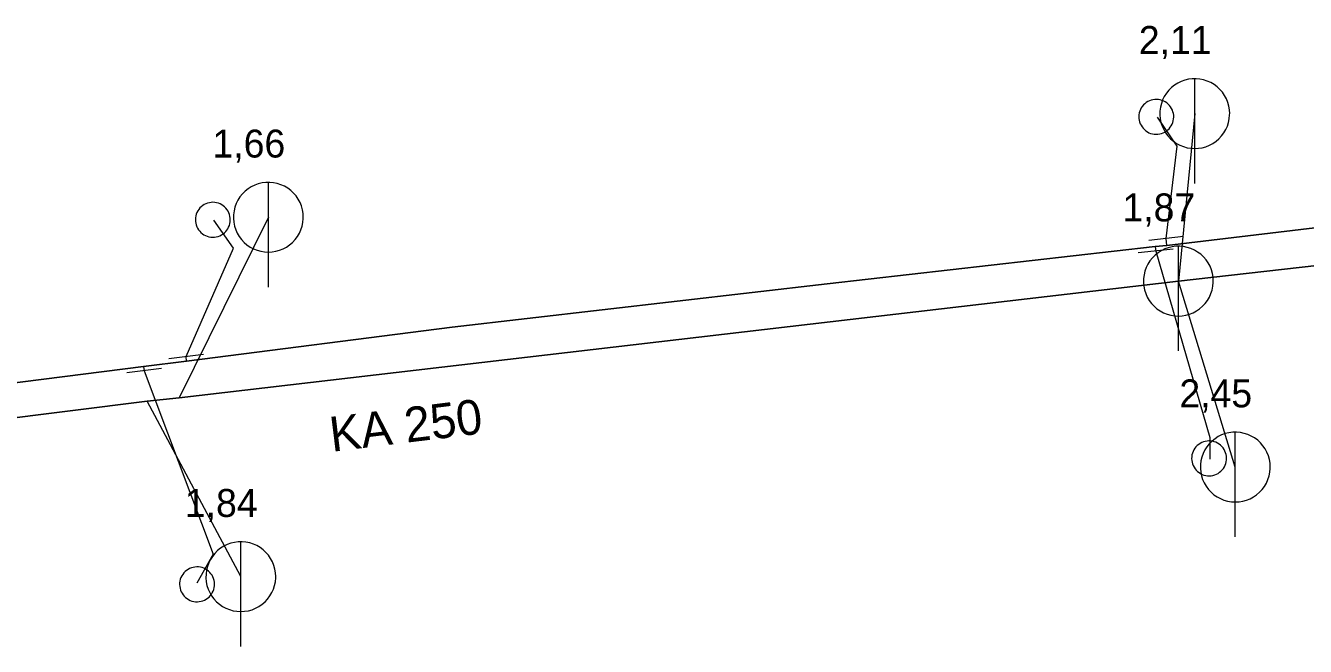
# Model space of a CAD drawing. Extents: x -682839 to -682312, y -994645 to -993949.
# Drawn here: x -682654.47 to -682617.83, y -994270.55 to -994252.76 of the extents above; entities that cross this region are included whole.
import ezdxf

# ---------------------------------------------------------------- set-up
doc = ezdxf.new("R2010")
doc.units = 0
doc.header["$LTSCALE"] = 0.4
doc.layers.add('1', color=7, linetype='Continuous')
for name, color, linetype, lineweight in [('11', 7, 'Continuous', 13), ('13', 7, 'Continuous', 13), ('14', 7, 'Continuous', 25), ('17', 7, 'Continuous', 25), ('22', 7, 'Continuous', 13), ('23', 7, 'Continuous', 13), ('34', 7, 'Continuous', 13)]:
    doc.layers.add(name, color=color, linetype=linetype, lineweight=lineweight)

msp = doc.modelspace()

# ---------------------------------------------------------------- linework, layer by layer
at = {"layer": '11'}
for p, q in [((-682621, -994255.28), (-682621.469, -994260.079)), ((-682647.52, -994258.25), (-682650.07, -994263.421)), ((-682619.84, -994265.41), (-682621.469, -994260.079)), ((-682648.309, -994268.55), (-682650.991, -994263.524))]:
    msp.add_line(p, q, dxfattribs=at)
at = {"layer": '13'}
for points in [[(-682621.819, -994258.859), (-682621.5, -994256.21), (-682622.069, -994255.379)], [(-682649.876, -994262.245), (-682648.52, -994259.14), (-682649.079, -994258.329)], [(-682622.119, -994259.219), (-682620.57, -994264.559), (-682620.567, -994265.183)], [(-682651.079, -994262.649), (-682649.1, -994267.91), (-682649.57, -994268.739)]]:
    msp.add_lwpolyline(points, dxfattribs=at)
at = {"layer": '14'}
msp.add_line((-682595.359, -994257.109), (-682621.469, -994260.079), dxfattribs=at)
at = {"layer": '14', "lineweight": 13}
for p, q in [((-682622.134, -994259.092), (-682622.119, -994259.219)), ((-682621.798, -994259.055), (-682621.819, -994258.859)), ((-682649.861, -994262.37), (-682649.876, -994262.245)), ((-682651.096, -994262.526), (-682651.079, -994262.649))]:
    msp.add_line(p, q, dxfattribs=at)
at = {"layer": '14'}
msp.add_lwpolyline([(-682621.469, -994260.079), (-682650.07, -994263.421), (-682650.991, -994263.524), (-682664.452, -994265.215)], dxfattribs=at)
at = {"layer": '17'}
msp.add_lwpolyline([(-682575, -994253.756), (-682585.09, -994254.838), (-682594.877, -994255.783), (-682595.977, -994255.888), (-682601.16, -994256.39), (-682606.69, -994257.25), (-682621.798, -994259.055), (-682622.134, -994259.092), (-682631.52, -994260.16), (-682642.26, -994261.399), (-682649.861, -994262.37), (-682651.096, -994262.526), (-682656.289, -994263.19), (-682658.389, -994263.379)], dxfattribs=at)
at = {"layer": '22'}
for p, q in [((-682621, -994257.28), (-682620.999, -994254.28)), ((-682647.52, -994260.25), (-682647.519, -994257.25)), ((-682621.47, -994262.08), (-682621.469, -994259.08)), ((-682619.84, -994267.41), (-682619.839, -994264.41)), ((-682648.309, -994270.55), (-682648.308, -994267.55))]:
    msp.add_line(p, q, dxfattribs=at)
for points in [[(-682620, -994255.28), (-682620.005, -994255.171), (-682620.023, -994255.063), (-682620.053, -994254.957), (-682620.093, -994254.856), (-682620.145, -994254.759), (-682620.207, -994254.669), (-682620.279, -994254.586), (-682620.359, -994254.512), (-682620.447, -994254.446), (-682620.541, -994254.391), (-682620.641, -994254.346), (-682620.746, -994254.313), (-682620.853, -994254.291), (-682620.962, -994254.281), (-682621.072, -994254.283), (-682621.18, -994254.297), (-682621.287, -994254.322), (-682621.39, -994254.359), (-682621.488, -994254.408), (-682621.58, -994254.466), (-682621.666, -994254.535), (-682621.743, -994254.612), (-682621.812, -994254.698), (-682621.871, -994254.79), (-682621.919, -994254.888), (-682621.956, -994254.991), (-682621.982, -994255.098), (-682621.996, -994255.206), (-682621.999, -994255.316), (-682621.989, -994255.425), (-682621.968, -994255.532), (-682621.934, -994255.636), (-682621.89, -994255.736), (-682621.835, -994255.831), (-682621.769, -994255.919), (-682621.695, -994255.999), (-682621.612, -994256.071), (-682621.522, -994256.133), (-682621.426, -994256.185), (-682621.324, -994256.226), (-682621.219, -994256.256), (-682621.111, -994256.274), (-682621.001, -994256.28), (-682620.892, -994256.274), (-682620.784, -994256.256), (-682620.679, -994256.227), (-682620.577, -994256.186), (-682620.48, -994256.134), (-682620.39, -994256.072), (-682620.307, -994256.001), (-682620.232, -994255.921), (-682620.167, -994255.833), (-682620.111, -994255.739), (-682620.067, -994255.639), (-682620.033, -994255.535), (-682620.011, -994255.427), (-682620.001, -994255.318)], [(-682646.52, -994258.25), (-682646.525, -994258.141), (-682646.543, -994258.033), (-682646.573, -994257.927), (-682646.613, -994257.826), (-682646.665, -994257.729), (-682646.727, -994257.639), (-682646.799, -994257.556), (-682646.879, -994257.482), (-682646.967, -994257.416), (-682647.061, -994257.361), (-682647.161, -994257.316), (-682647.266, -994257.283), (-682647.373, -994257.261), (-682647.482, -994257.251), (-682647.592, -994257.253), (-682647.7, -994257.267), (-682647.807, -994257.292), (-682647.91, -994257.329), (-682648.008, -994257.378), (-682648.1, -994257.436), (-682648.186, -994257.505), (-682648.263, -994257.582), (-682648.332, -994257.668), (-682648.391, -994257.76), (-682648.439, -994257.858), (-682648.476, -994257.961), (-682648.502, -994258.068), (-682648.516, -994258.176), (-682648.519, -994258.286), (-682648.509, -994258.395), (-682648.488, -994258.502), (-682648.454, -994258.606), (-682648.41, -994258.706), (-682648.355, -994258.801), (-682648.289, -994258.889), (-682648.215, -994258.969), (-682648.132, -994259.041), (-682648.042, -994259.103), (-682647.946, -994259.155), (-682647.844, -994259.196), (-682647.739, -994259.226), (-682647.631, -994259.244), (-682647.521, -994259.25), (-682647.412, -994259.244), (-682647.304, -994259.226), (-682647.199, -994259.197), (-682647.097, -994259.156), (-682647, -994259.104), (-682646.91, -994259.042), (-682646.827, -994258.971), (-682646.752, -994258.891), (-682646.687, -994258.803), (-682646.631, -994258.709), (-682646.587, -994258.609), (-682646.553, -994258.505), (-682646.531, -994258.397), (-682646.521, -994258.288)], [(-682620.47, -994260.08), (-682620.475, -994259.971), (-682620.493, -994259.863), (-682620.523, -994259.757), (-682620.563, -994259.656), (-682620.615, -994259.559), (-682620.677, -994259.469), (-682620.749, -994259.386), (-682620.829, -994259.312), (-682620.917, -994259.246), (-682621.011, -994259.191), (-682621.111, -994259.146), (-682621.216, -994259.113), (-682621.323, -994259.091), (-682621.432, -994259.081), (-682621.542, -994259.083), (-682621.65, -994259.097), (-682621.757, -994259.122), (-682621.86, -994259.159), (-682621.958, -994259.208), (-682622.05, -994259.266), (-682622.136, -994259.335), (-682622.213, -994259.412), (-682622.282, -994259.498), (-682622.341, -994259.59), (-682622.389, -994259.688), (-682622.426, -994259.791), (-682622.452, -994259.898), (-682622.466, -994260.006), (-682622.469, -994260.116), (-682622.459, -994260.225), (-682622.438, -994260.332), (-682622.404, -994260.436), (-682622.36, -994260.536), (-682622.305, -994260.631), (-682622.239, -994260.719), (-682622.165, -994260.799), (-682622.082, -994260.871), (-682621.992, -994260.933), (-682621.896, -994260.985), (-682621.794, -994261.026), (-682621.689, -994261.056), (-682621.581, -994261.074), (-682621.471, -994261.08), (-682621.362, -994261.074), (-682621.254, -994261.056), (-682621.149, -994261.027), (-682621.047, -994260.986), (-682620.95, -994260.934), (-682620.86, -994260.872), (-682620.777, -994260.801), (-682620.702, -994260.721), (-682620.637, -994260.633), (-682620.581, -994260.539), (-682620.537, -994260.439), (-682620.503, -994260.335), (-682620.481, -994260.227), (-682620.471, -994260.118)], [(-682618.84, -994265.41), (-682618.845, -994265.301), (-682618.863, -994265.193), (-682618.893, -994265.087), (-682618.933, -994264.986), (-682618.985, -994264.889), (-682619.047, -994264.799), (-682619.119, -994264.716), (-682619.199, -994264.642), (-682619.287, -994264.576), (-682619.381, -994264.521), (-682619.481, -994264.476), (-682619.586, -994264.443), (-682619.693, -994264.421), (-682619.802, -994264.411), (-682619.912, -994264.413), (-682620.02, -994264.427), (-682620.127, -994264.452), (-682620.23, -994264.489), (-682620.328, -994264.538), (-682620.42, -994264.596), (-682620.506, -994264.665), (-682620.583, -994264.742), (-682620.652, -994264.828), (-682620.711, -994264.92), (-682620.759, -994265.018), (-682620.796, -994265.121), (-682620.822, -994265.228), (-682620.836, -994265.336), (-682620.839, -994265.446), (-682620.829, -994265.555), (-682620.808, -994265.662), (-682620.774, -994265.766), (-682620.73, -994265.866), (-682620.675, -994265.961), (-682620.609, -994266.049), (-682620.535, -994266.129), (-682620.452, -994266.201), (-682620.362, -994266.263), (-682620.266, -994266.315), (-682620.164, -994266.356), (-682620.059, -994266.386), (-682619.951, -994266.404), (-682619.841, -994266.41), (-682619.732, -994266.404), (-682619.624, -994266.386), (-682619.519, -994266.357), (-682619.417, -994266.316), (-682619.32, -994266.264), (-682619.23, -994266.202), (-682619.147, -994266.131), (-682619.072, -994266.051), (-682619.007, -994265.963), (-682618.951, -994265.869), (-682618.907, -994265.769), (-682618.873, -994265.665), (-682618.851, -994265.557), (-682618.841, -994265.448)], [(-682647.309, -994268.55), (-682647.314, -994268.441), (-682647.332, -994268.333), (-682647.362, -994268.227), (-682647.402, -994268.126), (-682647.454, -994268.029), (-682647.516, -994267.939), (-682647.588, -994267.856), (-682647.668, -994267.782), (-682647.756, -994267.716), (-682647.85, -994267.661), (-682647.95, -994267.616), (-682648.055, -994267.583), (-682648.162, -994267.561), (-682648.271, -994267.551), (-682648.381, -994267.553), (-682648.489, -994267.567), (-682648.596, -994267.592), (-682648.699, -994267.629), (-682648.797, -994267.678), (-682648.889, -994267.736), (-682648.975, -994267.805), (-682649.052, -994267.882), (-682649.121, -994267.968), (-682649.18, -994268.06), (-682649.228, -994268.158), (-682649.265, -994268.261), (-682649.291, -994268.368), (-682649.305, -994268.476), (-682649.308, -994268.586), (-682649.298, -994268.695), (-682649.277, -994268.802), (-682649.243, -994268.906), (-682649.199, -994269.006), (-682649.144, -994269.101), (-682649.078, -994269.189), (-682649.004, -994269.269), (-682648.921, -994269.341), (-682648.831, -994269.403), (-682648.735, -994269.455), (-682648.633, -994269.496), (-682648.528, -994269.526), (-682648.42, -994269.544), (-682648.31, -994269.55), (-682648.201, -994269.544), (-682648.093, -994269.526), (-682647.988, -994269.497), (-682647.886, -994269.456), (-682647.789, -994269.404), (-682647.699, -994269.342), (-682647.616, -994269.271), (-682647.541, -994269.191), (-682647.476, -994269.103), (-682647.42, -994269.009), (-682647.376, -994268.909), (-682647.342, -994268.805), (-682647.32, -994268.697), (-682647.31, -994268.588)]]:
    msp.add_lwpolyline(points, close=True, dxfattribs=at)
at = {"layer": '23'}
for points in [[(-682621.813, -994255.782), (-682621.771, -994255.749), (-682621.733, -994255.712), (-682621.701, -994255.672), (-682621.672, -994255.629), (-682621.647, -994255.583), (-682621.628, -994255.533), (-682621.614, -994255.483), (-682621.605, -994255.433), (-682621.601, -994255.38), (-682621.603, -994255.328), (-682621.61, -994255.276), (-682621.623, -994255.224), (-682621.641, -994255.176), (-682621.664, -994255.13), (-682621.691, -994255.085), (-682621.725, -994255.043), (-682621.759, -994255.006), (-682621.801, -994254.972), (-682621.843, -994254.943), (-682621.889, -994254.918), (-682621.94, -994254.899), (-682621.989, -994254.885), (-682622.042, -994254.876), (-682622.093, -994254.872), (-682622.145, -994254.874), (-682622.198, -994254.882), (-682622.247, -994254.895), (-682622.297, -994254.913), (-682622.344, -994254.937), (-682622.388, -994254.964), (-682622.429, -994254.995), (-682622.467, -994255.032), (-682622.501, -994255.073), (-682622.53, -994255.116), (-682622.553, -994255.162), (-682622.573, -994255.21), (-682622.588, -994255.261), (-682622.597, -994255.313), (-682622.6, -994255.365)], [(-682621.801, -994254.972), (-682621.843, -994254.943), (-682621.889, -994254.918), (-682621.94, -994254.899), (-682621.989, -994254.885), (-682622.042, -994254.876), (-682622.093, -994254.872), (-682622.145, -994254.874), (-682622.198, -994254.882), (-682622.247, -994254.895), (-682622.297, -994254.913), (-682622.344, -994254.937), (-682622.388, -994254.964), (-682622.429, -994254.995), (-682622.467, -994255.032), (-682622.501, -994255.073), (-682622.53, -994255.116), (-682622.553, -994255.162), (-682622.573, -994255.21), (-682622.588, -994255.261), (-682622.597, -994255.313), (-682622.6, -994255.365), (-682622.599, -994255.416), (-682622.591, -994255.469), (-682622.579, -994255.519), (-682622.559, -994255.569), (-682622.536, -994255.615), (-682622.509, -994255.659), (-682622.477, -994255.7), (-682622.441, -994255.738), (-682622.4, -994255.773), (-682622.357, -994255.801), (-682622.31, -994255.826), (-682622.263, -994255.846), (-682622.211, -994255.859), (-682622.161, -994255.869), (-682622.109, -994255.872), (-682622.055, -994255.87), (-682622.003, -994255.863), (-682621.953, -994255.85)], [(-682622.6, -994255.365), (-682622.599, -994255.416), (-682622.591, -994255.469), (-682622.579, -994255.519), (-682622.559, -994255.569), (-682622.536, -994255.615), (-682622.509, -994255.659), (-682622.477, -994255.7), (-682622.441, -994255.738), (-682622.4, -994255.773), (-682622.357, -994255.801), (-682622.31, -994255.826), (-682622.263, -994255.846), (-682622.211, -994255.859), (-682622.161, -994255.869), (-682622.109, -994255.872), (-682622.055, -994255.87), (-682622.003, -994255.863), (-682621.953, -994255.85), (-682621.904, -994255.831), (-682621.857, -994255.809), (-682621.813, -994255.782), (-682621.771, -994255.749), (-682621.733, -994255.712), (-682621.701, -994255.672), (-682621.672, -994255.629), (-682621.647, -994255.583), (-682621.628, -994255.533), (-682621.614, -994255.483), (-682621.605, -994255.433), (-682621.601, -994255.38), (-682621.603, -994255.328), (-682621.61, -994255.276), (-682621.623, -994255.224), (-682621.641, -994255.176), (-682621.664, -994255.13), (-682621.691, -994255.085), (-682621.725, -994255.043), (-682621.759, -994255.006), (-682621.801, -994254.972)], [(-682621.953, -994255.85), (-682621.904, -994255.831), (-682621.857, -994255.809), (-682621.813, -994255.782)], [(-682648.822, -994258.731), (-682648.78, -994258.698), (-682648.742, -994258.661), (-682648.71, -994258.621), (-682648.681, -994258.578), (-682648.657, -994258.532), (-682648.637, -994258.482), (-682648.623, -994258.432), (-682648.615, -994258.381), (-682648.611, -994258.329), (-682648.613, -994258.277), (-682648.62, -994258.224), (-682648.634, -994258.173), (-682648.651, -994258.124), (-682648.675, -994258.078), (-682648.702, -994258.034), (-682648.736, -994257.992), (-682648.771, -994257.955), (-682648.813, -994257.921), (-682648.854, -994257.893), (-682648.901, -994257.868), (-682648.951, -994257.849), (-682649.001, -994257.835), (-682649.053, -994257.826), (-682649.105, -994257.822), (-682649.157, -994257.824), (-682649.209, -994257.833), (-682649.259, -994257.845), (-682649.308, -994257.864), (-682649.355, -994257.887), (-682649.399, -994257.915), (-682649.44, -994257.947), (-682649.478, -994257.984), (-682649.512, -994258.024), (-682649.541, -994258.067), (-682649.564, -994258.113), (-682649.583, -994258.162), (-682649.598, -994258.212), (-682649.607, -994258.265), (-682649.61, -994258.317)], [(-682648.813, -994257.921), (-682648.854, -994257.893), (-682648.901, -994257.868), (-682648.951, -994257.849), (-682649.001, -994257.835), (-682649.053, -994257.826), (-682649.105, -994257.822), (-682649.157, -994257.824), (-682649.209, -994257.833), (-682649.259, -994257.845), (-682649.308, -994257.864), (-682649.355, -994257.887), (-682649.399, -994257.915), (-682649.44, -994257.947), (-682649.478, -994257.984), (-682649.512, -994258.024), (-682649.541, -994258.067), (-682649.564, -994258.113), (-682649.583, -994258.162), (-682649.598, -994258.212), (-682649.607, -994258.265), (-682649.61, -994258.317), (-682649.609, -994258.368), (-682649.6, -994258.421), (-682649.589, -994258.471), (-682649.569, -994258.52), (-682649.546, -994258.566), (-682649.519, -994258.611), (-682649.486, -994258.651), (-682649.45, -994258.69), (-682649.409, -994258.724), (-682649.365, -994258.752), (-682649.319, -994258.777), (-682649.271, -994258.796), (-682649.22, -994258.809), (-682649.169, -994258.819), (-682649.117, -994258.822), (-682649.064, -994258.82), (-682649.012, -994258.813), (-682648.961, -994258.799)], [(-682649.61, -994258.317), (-682649.609, -994258.368), (-682649.6, -994258.421), (-682649.589, -994258.471), (-682649.569, -994258.52), (-682649.546, -994258.566), (-682649.519, -994258.611), (-682649.486, -994258.651), (-682649.45, -994258.69), (-682649.409, -994258.724), (-682649.365, -994258.752), (-682649.319, -994258.777), (-682649.271, -994258.796), (-682649.22, -994258.809), (-682649.169, -994258.819), (-682649.117, -994258.822), (-682649.064, -994258.82), (-682649.012, -994258.813), (-682648.961, -994258.799), (-682648.913, -994258.78), (-682648.866, -994258.758), (-682648.822, -994258.731), (-682648.78, -994258.698), (-682648.742, -994258.661), (-682648.71, -994258.621), (-682648.681, -994258.578), (-682648.657, -994258.532), (-682648.637, -994258.482), (-682648.623, -994258.432), (-682648.615, -994258.381), (-682648.611, -994258.329), (-682648.613, -994258.277), (-682648.62, -994258.224), (-682648.634, -994258.173), (-682648.651, -994258.124), (-682648.675, -994258.078), (-682648.702, -994258.034), (-682648.736, -994257.992), (-682648.771, -994257.955), (-682648.813, -994257.921)], [(-682648.961, -994258.799), (-682648.913, -994258.78), (-682648.866, -994258.758), (-682648.822, -994258.731)], [(-682620.117, -994264.997), (-682620.135, -994264.95), (-682620.159, -994264.903), (-682620.19, -994264.859), (-682620.223, -994264.819), (-682620.261, -994264.783), (-682620.301, -994264.75), (-682620.345, -994264.723), (-682620.394, -994264.7), (-682620.442, -994264.682), (-682620.493, -994264.669), (-682620.545, -994264.662), (-682620.597, -994264.66), (-682620.649, -994264.663), (-682620.701, -994264.672), (-682620.752, -994264.686), (-682620.8, -994264.705), (-682620.844, -994264.73), (-682620.888, -994264.76), (-682620.929, -994264.793), (-682620.966, -994264.831), (-682620.998, -994264.872), (-682621.026, -994264.915), (-682621.049, -994264.963), (-682621.068, -994265.011), (-682621.079, -994265.063), (-682621.086, -994265.114), (-682621.089, -994265.166), (-682621.085, -994265.218), (-682621.077, -994265.27), (-682621.063, -994265.321), (-682621.042, -994265.369), (-682621.018, -994265.416), (-682620.99, -994265.459), (-682620.955, -994265.499), (-682620.919, -994265.536), (-682620.878, -994265.568), (-682620.833, -994265.596), (-682620.786, -994265.619), (-682620.737, -994265.637)], [(-682620.998, -994264.872), (-682621.026, -994264.915), (-682621.049, -994264.963), (-682621.068, -994265.011), (-682621.079, -994265.063), (-682621.086, -994265.114), (-682621.089, -994265.166), (-682621.085, -994265.218), (-682621.077, -994265.27), (-682621.063, -994265.321), (-682621.042, -994265.369), (-682621.018, -994265.416), (-682620.99, -994265.459), (-682620.955, -994265.499), (-682620.919, -994265.536), (-682620.878, -994265.568), (-682620.833, -994265.596), (-682620.786, -994265.619), (-682620.737, -994265.637), (-682620.686, -994265.649), (-682620.634, -994265.657), (-682620.582, -994265.66), (-682620.529, -994265.656), (-682620.478, -994265.647), (-682620.429, -994265.632), (-682620.38, -994265.613), (-682620.334, -994265.589), (-682620.29, -994265.559), (-682620.25, -994265.525), (-682620.214, -994265.488), (-682620.181, -994265.447), (-682620.153, -994265.403), (-682620.129, -994265.356), (-682620.112, -994265.306), (-682620.099, -994265.256), (-682620.092, -994265.205), (-682620.089, -994265.153), (-682620.093, -994265.099), (-682620.101, -994265.049), (-682620.117, -994264.997)], [(-682620.582, -994265.66), (-682620.529, -994265.656), (-682620.478, -994265.647), (-682620.429, -994265.632), (-682620.38, -994265.613), (-682620.334, -994265.589), (-682620.29, -994265.559), (-682620.25, -994265.525), (-682620.214, -994265.488), (-682620.181, -994265.447), (-682620.153, -994265.403), (-682620.129, -994265.356), (-682620.112, -994265.306), (-682620.099, -994265.256), (-682620.092, -994265.205), (-682620.089, -994265.153), (-682620.093, -994265.099), (-682620.101, -994265.049), (-682620.117, -994264.997), (-682620.135, -994264.95), (-682620.159, -994264.903), (-682620.19, -994264.859), (-682620.223, -994264.819), (-682620.261, -994264.783), (-682620.301, -994264.75), (-682620.345, -994264.723), (-682620.394, -994264.7), (-682620.442, -994264.682), (-682620.493, -994264.669), (-682620.545, -994264.662), (-682620.597, -994264.66), (-682620.649, -994264.663), (-682620.701, -994264.672), (-682620.752, -994264.686), (-682620.8, -994264.705), (-682620.844, -994264.73), (-682620.888, -994264.76), (-682620.929, -994264.793), (-682620.966, -994264.831), (-682620.998, -994264.872)], [(-682620.737, -994265.637), (-682620.686, -994265.649), (-682620.634, -994265.657), (-682620.582, -994265.66)], [(-682649.319, -994268.332), (-682649.367, -994268.309), (-682649.417, -994268.291), (-682649.467, -994268.28), (-682649.519, -994268.272), (-682649.57, -994268.27), (-682649.623, -994268.275), (-682649.675, -994268.284), (-682649.724, -994268.298), (-682649.773, -994268.318), (-682649.819, -994268.342), (-682649.863, -994268.371), (-682649.903, -994268.406), (-682649.939, -994268.443), (-682649.971, -994268.484), (-682649.999, -994268.528), (-682650.022, -994268.577), (-682650.04, -994268.624), (-682650.052, -994268.677), (-682650.06, -994268.726), (-682650.062, -994268.779), (-682650.057, -994268.833), (-682650.048, -994268.884), (-682650.033, -994268.935), (-682650.014, -994268.983), (-682649.989, -994269.028), (-682649.959, -994269.072), (-682649.926, -994269.111), (-682649.888, -994269.148), (-682649.846, -994269.179), (-682649.802, -994269.208), (-682649.756, -994269.231), (-682649.706, -994269.248), (-682649.655, -994269.261), (-682649.604, -994269.269), (-682649.552, -994269.269), (-682649.5, -994269.265), (-682649.448, -994269.257), (-682649.397, -994269.242), (-682649.349, -994269.222)], [(-682649.349, -994269.222), (-682649.303, -994269.198), (-682649.259, -994269.168), (-682649.219, -994269.136), (-682649.183, -994269.096), (-682649.152, -994269.055), (-682649.124, -994269.012), (-682649.102, -994268.964), (-682649.083, -994268.915), (-682649.07, -994268.864), (-682649.064, -994268.812), (-682649.061, -994268.76), (-682649.065, -994268.708), (-682649.075, -994268.656), (-682649.088, -994268.606), (-682649.108, -994268.558), (-682649.133, -994268.511), (-682649.163, -994268.468), (-682649.197, -994268.428), (-682649.235, -994268.392), (-682649.275, -994268.36), (-682649.319, -994268.332), (-682649.367, -994268.309), (-682649.417, -994268.291), (-682649.467, -994268.28), (-682649.519, -994268.272), (-682649.57, -994268.27), (-682649.623, -994268.275), (-682649.675, -994268.284), (-682649.724, -994268.298), (-682649.773, -994268.318), (-682649.819, -994268.342), (-682649.863, -994268.371), (-682649.903, -994268.406), (-682649.939, -994268.443), (-682649.971, -994268.484), (-682649.999, -994268.528), (-682650.022, -994268.577), (-682650.04, -994268.624), (-682650.052, -994268.677)], [(-682650.052, -994268.677), (-682650.06, -994268.726), (-682650.062, -994268.779), (-682650.057, -994268.833), (-682650.048, -994268.884), (-682650.033, -994268.935), (-682650.014, -994268.983), (-682649.989, -994269.028), (-682649.959, -994269.072), (-682649.926, -994269.111), (-682649.888, -994269.148), (-682649.846, -994269.179), (-682649.802, -994269.208), (-682649.756, -994269.231), (-682649.706, -994269.248), (-682649.655, -994269.261), (-682649.604, -994269.269), (-682649.552, -994269.269), (-682649.5, -994269.265), (-682649.448, -994269.257), (-682649.397, -994269.242), (-682649.349, -994269.222), (-682649.303, -994269.198), (-682649.259, -994269.168), (-682649.219, -994269.136), (-682649.183, -994269.096), (-682649.152, -994269.055), (-682649.124, -994269.012), (-682649.102, -994268.964), (-682649.083, -994268.915), (-682649.07, -994268.864), (-682649.064, -994268.812), (-682649.061, -994268.76), (-682649.065, -994268.708), (-682649.075, -994268.656), (-682649.088, -994268.606), (-682649.108, -994268.558), (-682649.133, -994268.511), (-682649.163, -994268.468), (-682649.197, -994268.428)], [(-682649.197, -994268.428), (-682649.235, -994268.392), (-682649.275, -994268.36), (-682649.319, -994268.332)]]:
    msp.add_lwpolyline(points, dxfattribs=at)
at = {"layer": '34'}
for p, q in [((-682621.322, -994258.802), (-682622.315, -994258.914)), ((-682621.622, -994259.163), (-682622.616, -994259.273)), ((-682649.38, -994262.181), (-682650.372, -994262.307)), ((-682650.583, -994262.584), (-682651.574, -994262.712))]:
    msp.add_line(p, q, dxfattribs=at)

# ---------------------------------------------------------------- texts
at = {"layer": '1'}
for s, p in [('2,11', (-682622.6, -994253.568)), ('1,66', (-682649.119, -994256.538)), ('1,87', (-682623.069, -994258.368)), ('2,45', (-682621.44, -994263.698)), ('1,84', (-682649.91, -994266.838))]:
    msp.add_text(s, height=0.8, dxfattribs=at).set_placement(p)
msp.add_text('KA 250', height=1, rotation=7, dxfattribs=at).set_placement((-682645.703, -994264.974))

doc.saveas('drawing.dxf')
